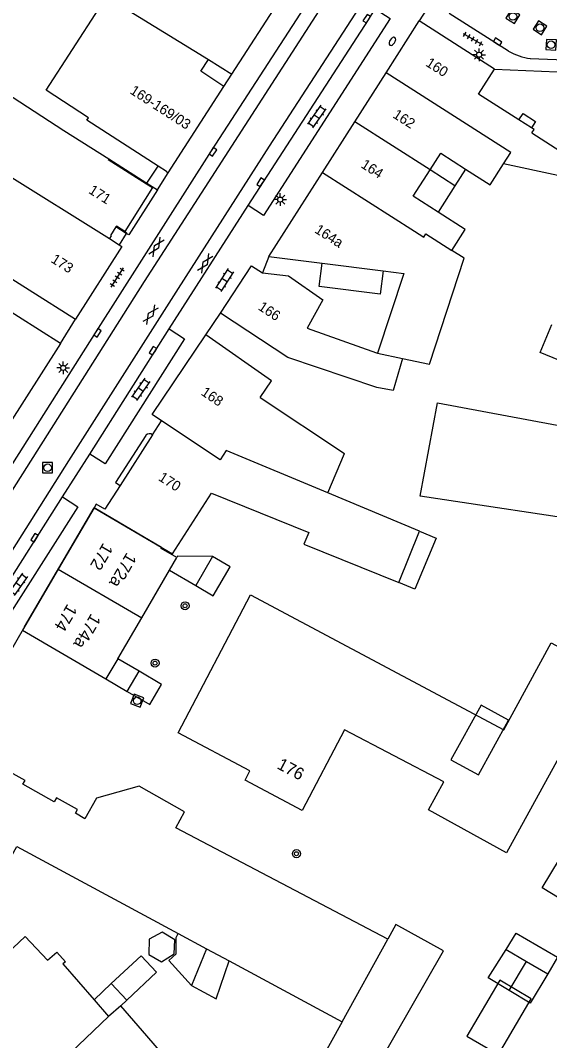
# Model space of a CAD drawing. Extents: x 132998 to 136004, y 396998 to 398512.
# Drawn here: x 133425.6 to 133478, y 397708.1 to 397809 of the extents above; entities that cross this region are included whole.
import ezdxf

# ---------------------------------------------------------------- set-up
doc = ezdxf.new("R2010")
doc.units = 0
for name, color, linetype in [('gg-afsc-erfafscheiding', 7, 'Continuous'), ('gg-afsc-hekwerk', 7, 'Continuous'), ('gg-afsc-muur', 7, 'Continuous'), ('gg-anno-huisnummerreeks BGT', 7, 'Continuous'), ('gg-bbg-gedigitaliseerde bebouwing', 7, 'Continuous'), ('gg-bbg-gedigitaliseerde bijgebouw', 7, 'Continuous'), ('gg-bbg-hoofdgebouw', 7, 'Continuous'), ('gg-bbg-luifel en loopbrug', 7, 'Continuous'), ('gg-bbg-onder overbouw', 7, 'Continuous'), ('gg-bbg-pand overbouw', 7, 'Continuous'), ('gg-bbg-tussenscheiding', 7, 'Continuous'), ('gg-knt-verharding', 7, 'Continuous'), ('gg-knt-verharding nz', 7, 'Continuous'), ('gt-anno-plantopografie huisnummer', 7, 'Continuous'), ('gt-bbg-plantopografie pand', 7, 'Continuous'), ('gt-bbg-plantopografie tussenscheiding', 7, 'Continuous'), ('gt-grn-vlakafsluiter', 7, 'Continuous'), ('gt-grn-weggrens', 7, 'Continuous'), ('gt-symb-boom', 7, 'Continuous'), ('gt-symb-brandkraan', 7, 'Continuous'), ('gt-symb-gesloten verharding', 7, 'Continuous'), ('gt-symb-klinker verharding', 7, 'Continuous'), ('gt-symb-kolk', 7, 'Continuous'), ('gt-symb-lichtmast', 7, 'Continuous'), ('gt-symb-rioolschacht', 7, 'Continuous'), ('gt-symb-tegel verharding', 7, 'Continuous')]:
    doc.layers.add(name, color=color, linetype=linetype)

# ---------------------------------------------------------------- blocks, each defined once
blk = doc.blocks.new('gt0-RS')
at = {"layer": 'gt-symb-rioolschacht'}
blk.add_lwpolyline([(-0.5, -0.5), (0.5, -0.5), (0.5, 0.5), (-0.5, 0.5)], close=True, dxfattribs=at)
blk.add_circle((0, 0), 0.375, dxfattribs=at)
blk = doc.blocks.new('gt0-LMAST')
at = {"layer": 'gt-symb-lichtmast'}
for p, q in [((-0.18, 0.17), (-0.45, 0.44)), ((-0.01, 0.25), (-0.01, 0.62)), ((0.17, 0.17), (0.44, 0.44)), ((-0.26, 0), (-0.63, 0)), ((-0.18, -0.18), (-0.45, -0.45)), ((-0.01, -0.25), (-0.01, -0.63)), ((0.44, -0.45), (0.17, -0.18)), ((0.24, 0), (0.62, 0))]:
    blk.add_line(p, q, dxfattribs=at)
blk.add_circle((-0.01, 0), 0.25, dxfattribs=at)
blk = doc.blocks.new('gt0-KOLK')
at = {"layer": 'gt-symb-kolk'}
blk.add_lwpolyline([(0, 0), (0.38, 0), (0.38, 0.4), (-0.37, 0.4), (-0.37, 0), (0, 0)], dxfattribs=at)
blk = doc.blocks.new('gt0-TEG1')
at = {"layer": 'gt-symb-tegel verharding'}
for p, q in [((-1.12, 0), (1.13, 0)), ((-0.9, -0.25), (-0.9, 0.25)), ((-0.45, -0.25), (-0.45, 0.25)), ((0, -0.25), (0, 0.25)), ((0.45, -0.25), (0.45, 0.25)), ((0.9, -0.25), (0.9, 0.25))]:
    blk.add_line(p, q, dxfattribs=at)
blk = doc.blocks.new('gt0-BR')
at = {"layer": 'gt-symb-brandkraan'}
for centre, radius, start, end in [((-0.24, 0), 0.206, 107.5669, 252.4331), ((0.6, -2.66), 3, 106.892, 107.5669), ((0, -0.69), 0.938, 73.108, 106.892), ((-0.6, -2.66), 3, 72.4331, 73.108), ((0.24, 0), 0.206, 287.567, 72.4331), ((0.6, 2.66), 3, 252.4331, 253.108), ((0, 0.69), 0.938, 253.108, 286.8921), ((-0.6, 2.66), 3, 286.8921, 287.567)]:
    blk.add_arc(centre, radius, start, end, dxfattribs=at)
blk = doc.blocks.new('gt0-KL1')
at = {"layer": 'gt-symb-klinker verharding'}
for p, q in [((-1.15, 0.3), (1.15, 0.3)), ((-1, -0.3), (-1, 0.3)), ((-0.5, 0.3), (-0.5, 0.45)), ((0, -0.3), (0, 0.3)), ((0.5, 0.3), (0.5, 0.45)), ((1, -0.3), (1, 0.3)), ((-1.15, -0.3), (1.15, -0.3)), ((-0.5, -0.45), (-0.5, -0.3)), ((0.5, -0.45), (0.5, -0.3))]:
    blk.add_line(p, q, dxfattribs=at)
blk = doc.blocks.new('gt0-GESVH1')
at = {"layer": 'gt-symb-gesloten verharding'}
for p, q in [((-0.99, -0.26), (0.01, 0.24)), ((0.01, -0.26), (-0.99, 0.24)), ((0.01, 0.24), (1.01, -0.26)), ((1.01, 0.24), (0.01, -0.26))]:
    blk.add_line(p, q, dxfattribs=at)
blk = doc.blocks.new('gt0-BOOM')
at = {"layer": 'gt-symb-boom'}
for radius in [0.4, 0.2]:
    blk.add_circle((0, 0), radius, dxfattribs=at)

msp = doc.modelspace()

# ---------------------------------------------------------------- linework, layer by layer
at = {"layer": 'gg-afsc-erfafscheiding'}
msp.add_line((133426.02, 397748.98), (133419.19, 397737.15), dxfattribs=at)
at = {"layer": 'gg-afsc-hekwerk'}
for p, q in [((133438.15, 397792.87), (133439.24, 397794.56)), ((133438.11, 397792.81), (133438.15, 397792.87))]:
    msp.add_line(p, q, dxfattribs=at)
at = {"layer": 'gg-afsc-muur'}
msp.add_line((133472.55, 397804.14), (133482.08, 397803.75), dxfattribs=at)
at = {"layer": 'gg-bbg-gedigitaliseerde bebouwing'}
for p, q in [((133476.19, 397798.34), (133474.96, 397799.13)), ((133476.23, 397797.84), (133479.01, 397796.07)), ((133478.81, 397793.64), (133473.44, 397794.79)), ((133450.22, 397785.63), (133455.48, 397784.96)), ((133455.48, 397784.96), (133461.51, 397784.2)), ((133461.51, 397784.2), (133463.58, 397783.94)), ((133463.58, 397783.94), (133460.97, 397776.06)), ((133450.48, 397773.32), (133443.98, 397777.88)), ((133449.36, 397771.68), (133450.48, 397773.32)), ((133449.36, 397771.68), (133457.69, 397766.14)), ((133456.06, 397762.24), (133457.69, 397766.14)), ((133465.13, 397758.46), (133456.06, 397762.24)), ((133463.06, 397753.38), (133465.13, 397758.46)), ((133461.97, 397718.11), (133441.02, 397729.11)), ((133444.05, 397717.15), (133446.28, 397715.94)), ((133446.28, 397715.94), (133457.45, 397709.93)), ((133432.92, 397712.1), (133434.34, 397710.46)), ((133435.55, 397711.51), (133434.34, 397710.46)), ((133438.14, 397708.52), (133435.55, 397711.51)), ((133439.8, 397706.63), (133438.14, 397708.52))]:
    msp.add_line(p, q, dxfattribs=at)
for points in [[(133418.98, 397820.64), (133415.24, 397814.69), (133412.59, 397816.36), (133409.66, 397811.66), (133412.01, 397810.2), (133411.81, 397809.87), (133429.91, 397798.1)], [(133474.96, 397799.13), (133470.97, 397801.68), (133472.55, 397804.14)], [(133476.23, 397797.84), (133476.45, 397798.18), (133476.19, 397798.34)], [(133466.17, 397794.18), (133467.22, 397795.84), (133469.67, 397794.27)], [(133469.67, 397794.27), (133472.11, 397792.71), (133473.44, 397794.79)], [(133466.95, 397790.01), (133464.5, 397791.58), (133466.17, 397794.18)], [(133468.32, 397786.22), (133469.65, 397788.29), (133466.95, 397790.01)], [(133463.43, 397775.54), (133466.1, 397774.98), (133469.54, 397785.44), (133468.32, 397786.22)], [(133452.14, 397783.72), (133455.56, 397781.32), (133453.99, 397778.54), (133460.86, 397776.09), (133460.97, 397776.06)], [(133463.43, 397775.54), (133462.52, 397772.35), (133460.88, 397772.67), (133452.1, 397775.64), (133445.42, 397780.02)], [(133432.91, 397760.75), (133440.68, 397756.2), (133444.55, 397762.21), (133454.15, 397758.33), (133453.68, 397757.17), (133463.06, 397753.38)], [(133431.06, 397730.55), (133431.27, 397730.91), (133429.19, 397732.09), (133428.96, 397731.69), (133425.87, 397733.43), (133426.09, 397733.79), (133423.77, 397735.09), (133423.55, 397734.69), (133419.19, 397737.15)], [(133441.02, 397729.11), (133441.86, 397730.7), (133437.38, 397733.23), (133433.17, 397732.05), (133432.01, 397730.01), (133431.06, 397730.55)], [(133424.74, 397726.31), (133425.28, 397727.27), (133441.25, 397718.66)], [(133457.45, 397709.93), (133452.19, 397700.4), (133456.51, 397697.77), (133467.48, 397716.93), (133462.76, 397719.55), (133461.97, 397718.11)], [(133422.67, 397714.37), (133424.14, 397715.75), (133423.75, 397716.16), (133426.1, 397718.37), (133428.31, 397716.02), (133429.24, 397716.82), (133430.07, 397715.87), (133429.83, 397715.66), (133432.92, 397712.1)]]:
    msp.add_lwpolyline(points, dxfattribs=at)
at = {"layer": 'gg-bbg-gedigitaliseerde bijgebouw'}
msp.add_line((133444.05, 397717.15), (133442.57, 397713.5), dxfattribs=at)
for points in [[(133480.06, 397778.15), (133478.92, 397775.37), (133477.07, 397776.13), (133478.21, 397778.9)], [(133483.55, 397759.15), (133465.19, 397761.93), (133466.89, 397771.14), (133485.1, 397767.76)], [(133468.23, 397735.84), (133470.94, 397734.34), (133473.93, 397739.76), (133471.21, 397741.24), (133468.23, 397735.84)], [(133442.57, 397713.5), (133440.3, 397715.97), (133441.03, 397716.65), (133441.04, 397718.27), (133441.25, 397718.66)], [(133473.05, 397714.03), (133469.81, 397708.51), (133472.95, 397706.68), (133476.18, 397712.2), (133473.05, 397714.03)]]:
    msp.add_lwpolyline(points, dxfattribs=at)
at = {"layer": 'gg-bbg-hoofdgebouw'}
for p, q in [((133446.53, 397803.66), (133452.99, 397813.62)), ((133461.82, 397803.79), (133465.09, 397808.92)), ((133472.55, 397804.14), (133465.09, 397808.92)), ((133444.23, 397805.09), (133446.53, 397803.66)), ((133458.72, 397798.94), (133461.82, 397803.79)), ((133440.26, 397793.9), (133445.74, 397802.43)), ((133455.52, 397793.92), (133458.72, 397798.94)), ((133429.91, 397798.1), (133434.36, 397795.28)), ((133440.08, 397794.02), (133439.24, 397794.56)), ((133440.08, 397794.02), (133440.26, 397793.9)), ((133450.22, 397785.63), (133455.52, 397793.92)), ((133434.45, 397787.41), (133435.4, 397786.79)), ((133435.65, 397786.62), (133431.08, 397779.43)), ((133435.4, 397786.79), (133435.65, 397786.62)), ((133449.59, 397784), (133452.14, 397783.72)), ((133429.58, 397777.03), (133420.38, 397782.84)), ((133429.58, 397777.03), (133424.32, 397768.75)), ((133438.69, 397767.98), (133439.58, 397769.37)), ((133438.69, 397767.98), (133435.48, 397762.98))]:
    msp.add_line(p, q, dxfattribs=at)
for points in [[(133439.24, 397794.56), (133432.21, 397799.09), (133432.35, 397799.32), (133428.17, 397802.06), (133433.39, 397810.11), (133433.73, 397809.89), (133434.52, 397811.12)], [(133445.74, 397802.43), (133443.48, 397803.94), (133444.23, 397805.09)], [(133435.08, 397788.55), (133434.54, 397787.71), (133434.61, 397787.66), (133434.45, 397787.41)], [(133420.38, 397782.84), (133421.88, 397785.24), (133431.08, 397779.43)], [(133445.42, 397780.02), (133448.49, 397784.71), (133449.59, 397784)], [(133439.58, 397769.37), (133438.65, 397769.99), (133443.98, 397777.88)], [(133435.48, 397762.98), (133433.97, 397760.64), (133433.12, 397761.11), (133432.91, 397760.75)]]:
    msp.add_lwpolyline(points, dxfattribs=at)
at = {"layer": 'gg-bbg-luifel en loopbrug'}
for p, q in [((133469.67, 397794.27), (133468.62, 397792.62)), ((133468.62, 397792.62), (133466.17, 397794.18)), ((133468.62, 397792.62), (133466.95, 397790.01)), ((133434.62, 397713.7), (133432.92, 397712.1)), ((133434.62, 397713.7), (133436.15, 397712.07)), ((133435.55, 397711.51), (133436.15, 397712.07))]:
    msp.add_line(p, q, dxfattribs=at)
for points in [[(133474.96, 397799.13), (133475.37, 397799.77), (133476.6, 397798.98), (133476.19, 397798.34)], [(133461.51, 397784.2), (133461.21, 397781.88), (133455.18, 397782.64), (133455.48, 397784.96)], [(133465.13, 397758.46), (133466.78, 397757.77), (133464.66, 397752.71), (133463.06, 397753.38)], [(133438.36, 397718.1), (133438.32, 397716.57), (133439.6, 397715.86), (133440.83, 397716.64), (133440.9, 397718.04), (133439.64, 397718.78), (133438.36, 397718.1)], [(133436.15, 397712.07), (133439.08, 397714.83), (133437.56, 397716.45), (133434.62, 397713.7)], [(133442.57, 397713.5), (133444.99, 397712.19), (133446.28, 397715.94)]]:
    msp.add_lwpolyline(points, dxfattribs=at)
at = {"layer": 'gg-bbg-onder overbouw'}
for points in [[(133434.36, 397795.28), (133434.32, 397795.22), (133438.11, 397792.81)], [(133438.11, 397792.81), (133438.71, 397792.43), (133435.96, 397788.09)], [(133435.96, 397788.09), (133435.12, 397788.62), (133435.08, 397788.55)]]:
    msp.add_lwpolyline(points, dxfattribs=at)
at = {"layer": 'gg-bbg-pand overbouw'}
for p, q in [((133434.36, 397795.28), (133438.15, 397792.87)), ((133438.15, 397792.87), (133439.19, 397792.21)), ((133436.1, 397787.91), (133435.08, 397788.55))]:
    msp.add_line(p, q, dxfattribs=at)
msp.add_lwpolyline([(133439.19, 397792.21), (133436.35, 397787.75), (133436.1, 397787.91)], dxfattribs=at)
at = {"layer": 'gg-bbg-tussenscheiding'}
for p, q in [((133434.52, 397811.12), (133444.23, 397805.09)), ((133466.17, 397794.18), (133458.72, 397798.94)), ((133423.97, 397793.93), (133434.45, 397787.41)), ((133460.97, 397776.06), (133463.43, 397775.54)), ((133441.25, 397718.66), (133444.05, 397717.15)), ((133457.45, 397709.93), (133461.97, 397718.11)), ((133429.84, 397706.15), (133434.34, 397710.46))]:
    msp.add_line(p, q, dxfattribs=at)
for points in [[(133473.44, 397794.79), (133474.16, 397795.91), (133461.82, 397803.79)], [(133455.52, 397793.92), (133464.61, 397788.11), (133465.53, 397787.53), (133465.75, 397787.86), (133468.32, 397786.22)], [(133456.06, 397762.24), (133446, 397766.43), (133445.38, 397765.51), (133439.58, 397769.37)]]:
    msp.add_lwpolyline(points, dxfattribs=at)
at = {"layer": 'gg-knt-verharding'}
for p, q in [((133466.23, 397810.71), (133465.09, 397808.92)), ((133468.04, 397809.7), (133473.93, 397805.95)), ((133445.74, 397802.43), (133446.53, 397803.66)), ((133440.36, 397778.45), (133448.17, 397790.66)), ((133436.1, 397787.91), (133435.4, 397786.79)), ((133450.22, 397785.63), (133449.59, 397784)), ((133429.58, 397777.03), (133431.08, 397779.43)), ((133443.98, 397777.88), (133445.42, 397780.02)), ((133432.5, 397766.07), (133440.36, 397778.45)), ((133429.8, 397761.84), (133432.5, 397766.07)), ((133418.72, 397744.43), (133429.8, 397761.84))]:
    msp.add_line(p, q, dxfattribs=at)
for points in [[(133458.53, 397817.7), (133444.51, 397796.08), (133433.08, 397778.18), (133420.25, 397757.95)], [(133448.17, 397790.66), (133460.06, 397809.03), (133460.74, 397810.13)], [(133460.74, 397810.13), (133462.23, 397809.16), (133449.68, 397789.68), (133448.17, 397790.66)], [(133476.08, 397805.2), (133482.07, 397804.96), (133482.08, 397803.75)], [(133440.36, 397778.45), (133441.85, 397777.47), (133434.02, 397765.1), (133432.5, 397766.07)], [(133438.04, 397767.93), (133435.04, 397763.26), (133435.48, 397762.98)], [(133429.8, 397761.84), (133431.3, 397760.86), (133420.24, 397743.47), (133418.72, 397744.43)]]:
    msp.add_lwpolyline(points, dxfattribs=at)
for centre, radius, start, end in [((133477.01, 397811.32), 6.2, 240.1931, 261.4468), ((133438.39, 397767.61), 0.475, 51.6518, 137.241)]:
    msp.add_arc(centre, radius, start, end, dxfattribs=at)
at = {"layer": 'gg-knt-verharding nz'}
for points in [[(133461.81, 397820.26), (133437.87, 397783.15), (133404.57, 397730.57)], [(133464.44, 397818.46), (133464.39, 397818.37), (133450.24, 397796.52), (133441.23, 397782.47), (133430.38, 397765.41), (133413.46, 397738.64), (133412.65, 397737.26), (133411.88, 397735.85), (133411.4, 397734.9), (133410.72, 397733.44), (133410.09, 397731.97), (133409.54, 397730.55), (133409.21, 397729.62), (133408.9, 397728.68), (133408.74, 397728.17)], [(133435.96, 397788.09), (133436.14, 397787.97), (133436.1, 397787.91)]]:
    msp.add_lwpolyline(points, dxfattribs=at)
at = {"layer": 'gt-bbg-plantopografie pand'}
for p, q in [((133432.91, 397760.75), (133429.37, 397754.71)), ((133437.63, 397749.88), (133440.38, 397754.59)), ((133440.38, 397754.59), (133442.98, 397753.07)), ((133435.25, 397745.82), (133437.63, 397749.88)), ((133437.36, 397744.59), (133435.25, 397745.82)), ((133434.09, 397743.84), (133436.2, 397742.6))]:
    msp.add_line(p, q, dxfattribs=at)
for points in [[(133441.11, 397755.84), (133439.56, 397756.75), (133439.6, 397756.83), (133432.91, 397760.75)], [(133444.64, 397755.96), (133441.18, 397755.97), (133441.11, 397755.84)], [(133442.98, 397753.07), (133444.71, 397752.05), (133446.39, 397754.94), (133444.64, 397755.96)], [(133429.37, 397754.71), (133425.84, 397748.67), (133434.09, 397743.84)], [(133441.22, 397738.5), (133448.39, 397752.15), (133473.45, 397738.81), (133478.14, 397747.4), (133485.04, 397743.71), (133481.25, 397736.88), (133479.78, 397737.69), (133473.72, 397726.65), (133466, 397730.9), (133467.54, 397733.66), (133457.7, 397738.81), (133453.52, 397730.82), (133447.85, 397733.82), (133448.34, 397734.75), (133441.22, 397738.5)], [(133436.2, 397742.6), (133438.42, 397741.3), (133439.58, 397743.29), (133437.36, 397744.59)], [(133481.38, 397720.66), (133477.25, 397723.17), (133481.64, 397730.44)], [(133473.68, 397717.09), (133474.69, 397718.7), (133478.78, 397716.31), (133477.81, 397714.68)], [(133473.99, 397713.02), (133471.92, 397714.27), (133473.68, 397717.09)], [(133477.81, 397714.68), (133476.07, 397711.78), (133473.99, 397713.02)]]:
    msp.add_lwpolyline(points, dxfattribs=at)
at = {"layer": 'gt-bbg-plantopografie tussenscheiding'}
for p, q in [((133444.64, 397755.96), (133442.98, 397753.07)), ((133440.38, 397754.59), (133441.11, 397755.84)), ((133429.37, 397754.71), (133437.63, 397749.88)), ((133435.25, 397745.82), (133434.09, 397743.84)), ((133436.2, 397742.6), (133437.36, 397744.59)), ((133473.68, 397717.09), (133475.72, 397715.9)), ((133473.99, 397713.02), (133475.72, 397715.9)), ((133475.72, 397715.9), (133477.81, 397714.68))]:
    msp.add_line(p, q, dxfattribs=at)
at = {"layer": 'gt-grn-vlakafsluiter'}
msp.add_line((133426.02, 397748.98), (133432.91, 397760.75), dxfattribs=at)
at = {"layer": 'gt-grn-weggrens'}
msp.add_line((133439.19, 397792.21), (133440.26, 397793.9), dxfattribs=at)

# ---------------------------------------------------------------- block references
at = {"layer": 'gt-symb-boom'}
for p in [(133441.92, 397751.07), (133438.95, 397745.4), (133452.94, 397726.55)]:
    msp.add_blockref('gt0-BOOM', p, dxfattribs=at)
at = {"layer": 'gt-symb-brandkraan', "rotation": 57.247560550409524}
msp.add_blockref('gt0-BR', (133462.43, 397806.9), dxfattribs=at)
at = {"layer": 'gt-symb-gesloten verharding'}
for p, rotation in [((133439.08, 397786.56), 57.454106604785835), ((133443.92, 397784.95), -122.54589339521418), ((133438.5, 397779.86), 55.3410637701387)]:
    msp.add_blockref('gt0-GESVH1', p, dxfattribs=dict(at, rotation=rotation))
at = {"layer": 'gt-symb-klinker verharding'}
for p, rotation in [((133454.95, 397799.47), -125.23135738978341), ((133445.82, 397783.3), -123.21354028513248), ((133437.53, 397772.48), -125.23135739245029), ((133425.42, 397753.2), -125.23135738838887)]:
    msp.add_blockref('gt0-KL1', p, dxfattribs=dict(at, rotation=rotation))
at = {"layer": 'gt-symb-kolk'}
for p, rotation in [((133460.06, 397809.03), 57.12021809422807), ((133472.74, 397806.7), -32.625035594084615), ((133444.51, 397796.08), -122.46679945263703), ((133449.56, 397792.85), 57.454106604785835), ((133433.08, 397778.18), -122.41844995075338), ((133438.91, 397776.19), 57.58155005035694), ((133427.18, 397757.69), 57.454106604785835)]:
    msp.add_blockref('gt0-KOLK', p, dxfattribs=dict(at, rotation=rotation))
at = {"layer": 'gt-symb-lichtmast'}
for p in [(133471.02, 397805.58), (133451.35, 397791.25), (133429.87, 397774.6)]:
    msp.add_blockref('gt0-LMAST', p, dxfattribs=at)
at = {"layer": 'gt-symb-rioolschacht'}
for p, rotation in [((133474.36, 397809.36), 148.32868147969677), ((133477.04, 397808.25), 147.99461679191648), ((133478.14, 397806.57), 176.73114704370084), ((133437.18, 397741.68), 68.90078774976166)]:
    msp.add_blockref('gt0-RS', p, dxfattribs=dict(at, rotation=rotation))
msp.add_blockref('gt0-RS', (133428.31, 397764.73), dxfattribs=at)
at = {"layer": 'gt-symb-tegel verharding'}
for p, rotation in [((133470.39, 397807.13), -30.128600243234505), ((133435.21, 397783.54), 57.454106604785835)]:
    msp.add_blockref('gt0-TEG1', p, dxfattribs=dict(at, rotation=rotation))

# ---------------------------------------------------------------- texts
at = {"layer": 'gg-anno-huisnummerreeks BGT'}
for s, rotation, p in [('160', 327.5, (133465.65, 397804.53)), ('169-169/03', 327.2, (133436.38, 397801.8)), ('162', 327.5, (133462.39, 397799.42)), ('164', 327.5, (133459.24, 397794.48)), ('171', 327.7, (133432.29, 397791.94)), ('164a', 327.5, (133454.66, 397788.04)), ('173', 327.6, (133428.57, 397785.11)), ('166', 326.8, (133449.07, 397780.42)), ('168', 326, (133443.42, 397771.99)), ('170', 327.2, (133439.2, 397763.54))]:
    msp.add_text(s, height=1, rotation=rotation, dxfattribs=at).set_placement(p)
at = {"layer": 'gt-anno-plantopografie huisnummer'}
for s, rotation, p in [('172', 239.6535, (133433.83, 397757.37)), ('172a', 239.6535, (133436.16, 397756.41)), ('174', 239.6535, (133430.29, 397751.33)), ('174a', 239.6535, (133432.63, 397750.37)), ('176', 332.1031, (133450.93, 397735.02))]:
    msp.add_text(s, height=1.2, rotation=rotation, dxfattribs=at).set_placement(p)

doc.saveas('drawing.dxf')
